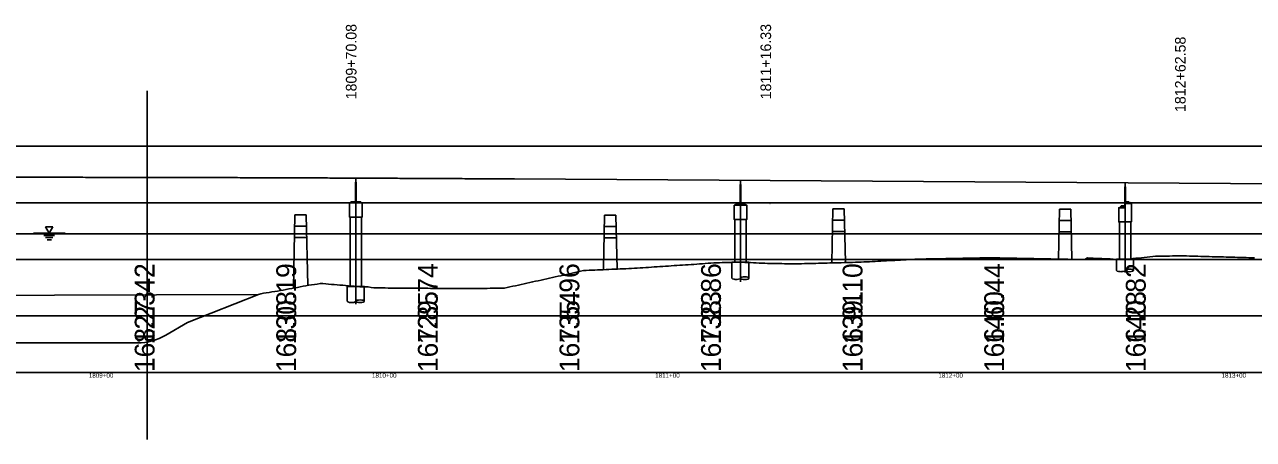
# Model space of a CAD drawing. Extents: x 2126510 to 2136144, y 865066 to 868066.
# Drawn here: x 2129321.8 to 2129755.8, y 866590.3 to 866736.8 of the extents above; entities that cross this region are included whole.
import ezdxf

# ---------------------------------------------------------------- set-up
doc = ezdxf.new("R2010")
doc.units = 0
for name, color, linetype in [('RD_DTM_BkLn1', 7, 'Continuous'), ('RD_EX_Bldg', 7, 'Continuous'), ('RD_EX_BldgApp', 7, 'Continuous'), ('RD_EX_Bridge', 7, 'Continuous'), ('RD_EX_GuardRail', 7, 'Continuous'), ('RD_EX_H2O', 7, 'Continuous'), ('RD_EX_Misc', 7, 'Continuous'), ('RD_EX_Misc_Golf_Fairway', 7, 'Continuous'), ('RD_HC_Data', 7, 'Continuous'), ('RD_HC_txCode', 7, 'Continuous')]:
    doc.layers.add(name, color=color, linetype=linetype)

msp = doc.modelspace()

# ---------------------------------------------------------------- linework, layer by layer
at = {"layer": 'RD_DTM_BkLn1'}
for p, q in [((2129440.54, 866674.17), (2129437.04, 866674.17)), ((2129437.04, 866674.17), (2129437.04, 866673.84)), ((2129437.46, 866674.17), (2129440.13, 866674.17)), ((2129440.54, 866673.84), (2129440.54, 866674.17)), ((2129576.38, 866673.37), (2129572.88, 866673.37)), ((2129572.88, 866673.37), (2129572.88, 866673.03)), ((2129573.29, 866673.37), (2129575.96, 866673.37)), ((2129576.38, 866673.03), (2129576.38, 866673.37)), ((2129710.46, 866673.97), (2129712.21, 866673.97)), ((2129710.46, 866673.97), (2129710.46, 866673.6)), ((2129710.46, 866672.14), (2129710.46, 866673.6)), ((2129712.71, 866673.6), (2129710.46, 866673.6)), ((2129712.21, 866673.97), (2129712.21, 866673.6)), ((2129436.79, 866668.84), (2129436.79, 866644.34)), ((2129440.79, 866668.84), (2129440.79, 866644.34)), ((2129710.46, 866672.51), (2129708.71, 866672.51)), ((2129708.71, 866672.51), (2129708.71, 866672.14)), ((2129572.63, 866668.03), (2129572.63, 866652.88)), ((2129576.63, 866668.03), (2129576.63, 866652.88)), ((2129708.46, 866667.14), (2129708.46, 866653.94)), ((2129712.46, 866667.14), (2129712.46, 866653.94))]:
    msp.add_line(p, q, dxfattribs=at)
for points in [[(2129436.54, 866673.84), (2129441.04, 866673.84), (2129441.04, 866668.84), (2129436.54, 866668.84)], [(2129572.38, 866673.03), (2129576.88, 866673.03), (2129576.88, 866668.03), (2129572.38, 866668.03)]]:
    msp.add_lwpolyline(points, close=True, dxfattribs=at)
for points in [[(2129712.71, 866673.6), (2129712.71, 866667.14), (2129708.21, 866667.14), (2129708.21, 866672.14), (2129710.46, 866672.14)], [(2129571.63, 866647.25), (2129571.63, 866652.88), (2129577.63, 866652.88), (2129577.63, 866647.25)], [(2129707.46, 866650), (2129707.46, 866653.94), (2129713.46, 866653.94), (2129713.46, 866650)], [(2129435.79, 866639.1), (2129435.79, 866644.34), (2129441.79, 866644.34), (2129441.79, 866639.1)]]:
    msp.add_lwpolyline(points, dxfattribs=at)
for centre in [(2129573.13, 866647.25), (2129708.96, 866650), (2129437.29, 866639.1)]:
    msp.add_ellipse(centre, major_axis=(-1.5, 0), ratio=0.310397, start_param=0, end_param=3.141593, dxfattribs=at)
for centre in [(2129576.13, 866647.25), (2129711.96, 866650), (2129440.29, 866639.1)]:
    msp.add_ellipse(centre, major_axis=(-1.5, 0), ratio=0.310397, dxfattribs=at)
at = {"layer": 'RD_EX_Bldg'}
for p, q in [((2129711.79, 866673.97), (2129710.46, 866673.97)), ((2129709.12, 866672.51), (2129710.46, 866672.51))]:
    msp.add_line(p, q, dxfattribs=at)
at = {"layer": 'RD_EX_BldgApp'}
for p, q in [((2129329.23, 866665.37), (2129331.85, 866665.37)), ((2129330.54, 866663.1), (2129329.23, 866665.37)), ((2129331.85, 866665.37), (2129330.54, 866663.1)), ((2129324.92, 866663.1), (2129336.17, 866663.1)), ((2129328.67, 866662.35), (2129332.42, 866662.35)), ((2129329.23, 866661.6), (2129331.85, 866661.6)), ((2129329.79, 866660.85), (2129331.29, 866660.85))]:
    msp.add_line(p, q, dxfattribs=at)
at = {"layer": 'RD_EX_Bridge'}
for p, q in [((2129437.46, 866674.46), (2129437.46, 866674.17)), ((2129438.46, 866674.46), (2129438.46, 866674.17)), ((2129439.13, 866674.17), (2129439.13, 866674.46)), ((2129440.13, 866674.17), (2129440.13, 866674.46)), ((2129573.29, 866673.66), (2129573.29, 866673.37)), ((2129574.29, 866673.66), (2129574.29, 866673.37)), ((2129574.96, 866673.37), (2129574.96, 866673.66)), ((2129575.96, 866673.37), (2129575.96, 866673.66)), ((2129710.12, 866672.8), (2129709.12, 866672.8)), ((2129709.12, 866672.8), (2129709.12, 866672.51)), ((2129710.12, 866672.8), (2129710.12, 866672.51)), ((2129710.79, 866674.26), (2129711.79, 866674.26)), ((2129710.79, 866673.97), (2129710.79, 866674.26)), ((2129711.79, 866674.26), (2129711.79, 866673.97))]:
    msp.add_line(p, q, dxfattribs=at)
at = {"layer": 'RD_EX_GuardRail'}
for p, q in [((2131097.7, 866693.9), (2126517.45, 866693.9)), ((2131097.7, 866673.9), (2129000.13, 866673.9)), ((2131097.7, 866653.9), (2126517.45, 866653.9)), ((2131097.7, 866633.9), (2126517.45, 866633.9)), ((2131097.7, 866613.9), (2126517.45, 866613.9))]:
    msp.add_line(p, q, dxfattribs=at)
at = {"layer": 'RD_EX_H2O'}
msp.add_line((2129043.31, 866624.4), (2129361.63, 866624.4), dxfattribs=at)
for points in [[(2129532.19, 866650.52), (2129533.19, 866650.56), (2129534.19, 866650.6), (2129535.19, 866650.65), (2129536.19, 866650.69), (2129537.19, 866650.74), (2129538.19, 866650.8), (2129539.19, 866650.86), (2129540.19, 866650.93), (2129541.19, 866651), (2129542.19, 866651.06), (2129543.19, 866651.13), (2129544.19, 866651.2), (2129545.19, 866651.27), (2129546.19, 866651.33), (2129547.19, 866651.4), (2129548.19, 866651.47), (2129549.19, 866651.53), (2129550.19, 866651.6), (2129551.19, 866651.67), (2129552.19, 866651.73), (2129553.19, 866651.8), (2129554.19, 866651.87), (2129555.19, 866651.93), (2129556.19, 866652), (2129557.19, 866652.07), (2129558.19, 866652.14), (2129559.19, 866652.2), (2129560.19, 866652.27), (2129561.19, 866652.37), (2129562.19, 866652.46), (2129563.19, 866652.56), (2129564.19, 866652.61), (2129565.19, 866652.64), (2129566.19, 866652.68), (2129567.19, 866652.71), (2129568.19, 866652.75), (2129569.19, 866652.78), (2129570.19, 866652.81), (2129571.19, 866652.83), (2129572.19, 866652.85), (2129573.19, 866652.87), (2129574.19, 866652.9), (2129575.19, 866652.87), (2129576.19, 866652.82), (2129577.19, 866652.78), (2129578.19, 866652.73), (2129579.19, 866652.69), (2129580.19, 866652.64), (2129581.19, 866652.6), (2129582.19, 866652.56), (2129583.19, 866652.51), (2129584.19, 866652.47), (2129585.19, 866652.42), (2129586.19, 866652.38), (2129587.19, 866652.38), (2129588.19, 866652.38), (2129589.19, 866652.38), (2129590.19, 866652.36), (2129591.19, 866652.34), (2129592.19, 866652.36), (2129593.19, 866652.36), (2129594.19, 866652.37), (2129595.19, 866652.37), (2129596.19, 866652.37), (2129597.19, 866652.39), (2129598.19, 866652.41), (2129599.19, 866652.44), (2129600.19, 866652.46), (2129601.19, 866652.49), (2129602.19, 866652.52), (2129603.19, 866652.54), (2129604.19, 866652.57), (2129605.19, 866652.59), (2129606.19, 866652.62), (2129607.19, 866652.65), (2129608.19, 866652.67), (2129609.19, 866652.7), (2129610.19, 866652.72), (2129611.19, 866652.75), (2129612.19, 866652.78), (2129613.19, 866652.8), (2129614.19, 866652.83), (2129615.19, 866652.85), (2129616.19, 866652.89), (2129617.19, 866652.92), (2129618.19, 866652.97), (2129619.19, 866653.02), (2129620.19, 866653.08), (2129621.19, 866653.13), (2129622.19, 866653.18), (2129623.19, 866653.23), (2129624.19, 866653.28), (2129625.19, 866653.34), (2129626.19, 866653.39), (2129627.19, 866653.44), (2129628.19, 866653.49), (2129629.19, 866653.55), (2129630.19, 866653.6), (2129631.19, 866653.65), (2129632.19, 866653.7)], [(2129632.19, 866653.7), (2129633.19, 866653.76), (2129634.19, 866653.81), (2129635.19, 866653.86), (2129636.19, 866653.91), (2129637.19, 866653.96), (2129638.19, 866653.99), (2129639.19, 866654.01), (2129640.19, 866654.03), (2129641.19, 866654.05), (2129642.19, 866654.07), (2129643.19, 866654.08), (2129644.19, 866654.1), (2129645.19, 866654.12), (2129646.19, 866654.14), (2129647.19, 866654.16), (2129648.19, 866654.18), (2129649.19, 866654.2), (2129650.19, 866654.21), (2129651.19, 866654.23), (2129652.19, 866654.25), (2129653.19, 866654.27), (2129654.19, 866654.29), (2129655.19, 866654.31), (2129656.19, 866654.32), (2129657.19, 866654.34), (2129658.19, 866654.36), (2129659.19, 866654.38), (2129660.19, 866654.4), (2129661.19, 866654.42), (2129662.19, 866654.45), (2129663.19, 866654.47), (2129664.19, 866654.45), (2129665.19, 866654.41), (2129666.19, 866654.39), (2129667.19, 866654.37), (2129668.19, 866654.35), (2129669.19, 866654.33), (2129670.19, 866654.31), (2129671.19, 866654.29), (2129672.19, 866654.27), (2129673.19, 866654.25), (2129674.19, 866654.23), (2129675.19, 866654.21), (2129676.19, 866654.19), (2129677.19, 866654.17), (2129678.19, 866654.15), (2129679.19, 866654.13), (2129680.19, 866654.12), (2129681.19, 866654.1), (2129682.19, 866654.08), (2129683.19, 866654.06), (2129684.19, 866654.04), (2129685.19, 866654.02), (2129686.19, 866654), (2129687.19, 866653.98), (2129688.19, 866653.96), (2129689.19, 866653.94), (2129690.19, 866653.92), (2129691.19, 866653.9), (2129692.19, 866653.88), (2129693.19, 866653.86), (2129694.19, 866653.84), (2129695.19, 866653.82), (2129696.19, 866653.85), (2129697.19, 866654.4), (2129698.19, 866654.35), (2129699.19, 866654.31), (2129700.19, 866654.26), (2129701.19, 866654.21), (2129702.19, 866654.17), (2129703.19, 866654.12), (2129704.19, 866654.07), (2129705.19, 866654.03), (2129706.19, 866653.97), (2129707.19, 866653.89), (2129708.19, 866653.81), (2129709.19, 866653.86), (2129710.19, 866653.92), (2129711.19, 866653.98), (2129712.19, 866654.08), (2129713.19, 866654.18), (2129714.19, 866654.28), (2129715.19, 866654.37), (2129716.19, 866654.47), (2129717.19, 866654.57), (2129718.19, 866654.67), (2129719.19, 866654.77), (2129720.19, 866654.87), (2129721.19, 866654.97), (2129722.19, 866655), (2129723.19, 866654.97), (2129724.19, 866655.01), (2129725.19, 866655.02), (2129726.19, 866655.05), (2129727.19, 866655.09), (2129728.19, 866655.13), (2129729.19, 866655.17), (2129730.19, 866655.14), (2129731.19, 866655.11), (2129732.19, 866655.09)], [(2129732.19, 866655.09), (2129733.19, 866655.06), (2129734.19, 866655.03), (2129735.19, 866655.01), (2129736.19, 866654.98), (2129737.19, 866654.95), (2129738.19, 866654.93), (2129739.19, 866654.9), (2129740.19, 866654.87), (2129741.19, 866654.84), (2129742.19, 866654.82), (2129743.19, 866654.79), (2129744.19, 866654.76), (2129745.19, 866654.74), (2129746.19, 866654.71), (2129747.19, 866654.68), (2129748.19, 866654.66), (2129749.19, 866654.63), (2129750.19, 866654.6), (2129751.19, 866654.57), (2129752.19, 866654.55), (2129753.19, 866654.52), (2129754.19, 866654.49), (2129755.19, 866654.47), (2129756.19, 866654.45)], [(2129432.19, 866644.9), (2129433.19, 866644.82), (2129434.19, 866644.73), (2129435.19, 866644.65), (2129436.19, 866644.56), (2129437.19, 866644.48), (2129438.19, 866644.39), (2129439.19, 866644.31), (2129440.19, 866644.22), (2129441.19, 866644.17), (2129442.19, 866644.17), (2129443.19, 866644.18), (2129444.19, 866643.98), (2129445.19, 866643.85), (2129446.19, 866643.83), (2129447.19, 866643.81), (2129448.19, 866643.79), (2129449.19, 866643.78), (2129450.19, 866643.77), (2129451.19, 866643.76), (2129452.19, 866643.76), (2129453.19, 866643.75), (2129454.19, 866643.74), (2129455.19, 866643.73), (2129456.19, 866643.73), (2129457.19, 866643.72), (2129458.19, 866643.71), (2129459.19, 866643.71), (2129460.19, 866643.7), (2129461.19, 866643.69), (2129462.19, 866643.69), (2129463.19, 866643.68), (2129464.19, 866643.67), (2129465.19, 866643.66), (2129466.19, 866643.66), (2129467.19, 866643.65), (2129468.19, 866643.64), (2129469.19, 866643.64), (2129470.19, 866643.63), (2129471.19, 866643.62), (2129472.19, 866643.62), (2129473.19, 866643.61), (2129474.19, 866643.6), (2129475.19, 866643.6), (2129476.19, 866643.59), (2129477.19, 866643.58), (2129478.19, 866643.57), (2129479.19, 866643.57), (2129480.19, 866643.56), (2129481.19, 866643.55), (2129482.19, 866643.55), (2129483.19, 866643.55), (2129484.19, 866643.59), (2129485.19, 866643.63), (2129486.19, 866643.67), (2129487.19, 866643.71), (2129488.19, 866643.73), (2129489.19, 866643.72), (2129490.19, 866643.71), (2129491.19, 866643.72), (2129492.19, 866643.94), (2129493.19, 866644.16), (2129494.19, 866644.38), (2129495.19, 866644.6), (2129496.19, 866644.82), (2129497.19, 866645.04), (2129498.19, 866645.26), (2129499.19, 866645.48), (2129500.19, 866645.7), (2129501.19, 866645.92), (2129502.19, 866646.15), (2129503.19, 866646.37), (2129504.19, 866646.59), (2129505.19, 866646.81), (2129506.19, 866647.03), (2129507.19, 866647.25), (2129508.19, 866647.47), (2129509.19, 866647.69), (2129510.19, 866647.91), (2129511.19, 866648.13), (2129512.19, 866648.35), (2129513.19, 866648.57), (2129514.19, 866648.79), (2129515.19, 866649.01), (2129516.19, 866649.26), (2129517.19, 866649.52), (2129518.19, 866649.78), (2129519.19, 866649.94), (2129520.19, 866649.99), (2129521.19, 866650.03), (2129522.19, 866650.08), (2129523.19, 866650.12), (2129524.19, 866650.16), (2129525.19, 866650.21), (2129526.19, 866650.25), (2129527.19, 866650.3), (2129528.19, 866650.34), (2129529.19, 866650.38), (2129530.19, 866650.43), (2129531.19, 866650.47), (2129532.19, 866650.52)], [(2129404.47, 866641.43), (2129405.19, 866641.67), (2129406.19, 866641.95), (2129407.19, 866642.09), (2129408.19, 866642.23), (2129409.19, 866642.37), (2129410.19, 866642.51), (2129411.19, 866642.68), (2129412.19, 866642.87), (2129413.19, 866643.06), (2129414.19, 866643.25), (2129415.19, 866643.43), (2129416.19, 866643.62), (2129417.19, 866643.81), (2129418.19, 866643.99), (2129419.19, 866644.18), (2129420.19, 866644.37), (2129421.19, 866644.56), (2129422.19, 866644.74), (2129423.19, 866644.9), (2129424.19, 866645.04), (2129425.19, 866645.19), (2129426.19, 866645.34), (2129427.19, 866645.32), (2129428.19, 866645.24), (2129429.19, 866645.15), (2129430.19, 866645.07), (2129431.19, 866644.99), (2129432.19, 866644.9)], [(2129404.47, 866641.43), (2129379.32, 866631.56), (2129371.69, 866627.12)]]:
    msp.add_lwpolyline(points, dxfattribs=at)
msp.add_arc((2129361.63, 866644.4), 20, 270, 300.189, dxfattribs=at)
at = {"layer": 'RD_EX_Misc'}
for p, q in [((2129365.16, 866713.42), (2129365.16, 866590.28)), ((2129494.88, 866682.29), (2130513.48, 866675.88)), ((2127368.72, 866613.9), (2131522.97, 866613.9))]:
    msp.add_line(p, q, dxfattribs=at)
for points in [[(2127275.85, 866613.9), (2127275.85, 866662.9), (2131989.68, 866662.9)], [(2129008.05, 866640.24), (2129404.47, 866641.43)]]:
    msp.add_lwpolyline(points, dxfattribs=at)
msp.add_spline([(2129142.37, 866682.52), (2129149.42, 866682.56), (2129156.47, 866682.59), (2129163.52, 866682.62), (2129170.57, 866682.65), (2129177.62, 866682.68), (2129184.67, 866682.7), (2129191.72, 866682.73), (2129198.77, 866682.75), (2129205.82, 866682.77), (2129212.87, 866682.79), (2129219.92, 866682.81), (2129226.97, 866682.83), (2129234.02, 866682.85), (2129241.07, 866682.86), (2129248.12, 866682.87), (2129255.17, 866682.88), (2129262.23, 866682.89), (2129269.28, 866682.9), (2129276.33, 866682.9), (2129283.38, 866682.91), (2129290.43, 866682.91), (2129297.48, 866682.91), (2129304.53, 866682.91), (2129311.58, 866682.91), (2129318.63, 866682.9), (2129325.68, 866682.9), (2129332.73, 866682.89), (2129339.78, 866682.88), (2129346.83, 866682.87), (2129353.88, 866682.86), (2129360.93, 866682.85), (2129367.98, 866682.83), (2129375.03, 866682.82), (2129382.08, 866682.8), (2129389.13, 866682.78), (2129396.18, 866682.76), (2129403.23, 866682.74), (2129410.28, 866682.71), (2129417.33, 866682.68), (2129424.38, 866682.66), (2129431.43, 866682.63), (2129438.48, 866682.6), (2129445.53, 866682.56), (2129452.58, 866682.53), (2129459.63, 866682.49), (2129466.68, 866682.46), (2129473.73, 866682.42), (2129480.78, 866682.38), (2129487.83, 866682.34), (2129494.88, 866682.29)], degree=3, dxfattribs=at)
at = {"layer": 'RD_EX_Misc_Golf_Fairway'}
for p, q in [((2129417.28, 866669.65), (2129416.74, 866643.72)), ((2129421.28, 866669.65), (2129417.28, 866669.65)), ((2129421.28, 866669.65), (2129421.8, 866644.67)), ((2129526.66, 866669.47), (2129526.26, 866650.26)), ((2129530.66, 866669.47), (2129526.66, 866669.47)), ((2129530.66, 866669.47), (2129531.05, 866650.47)), ((2129607.28, 866671.79), (2129606.88, 866652.64)), ((2129611.28, 866671.79), (2129607.28, 866671.79)), ((2129611.28, 866671.79), (2129611.68, 866652.76)), ((2129687.28, 866671.63), (2129686.92, 866653.98)), ((2129691.28, 866671.63), (2129687.28, 866671.63)), ((2129691.28, 866671.63), (2129691.65, 866653.89)), ((2129421.37, 866665.65), (2129417.21, 866665.65)), ((2129530.74, 866665.47), (2129526.59, 866665.47)), ((2129611.37, 866667.79), (2129607.21, 866667.79)), ((2129691.37, 866667.63), (2129687.21, 866667.63)), ((2129421.45, 866661.65), (2129417.12, 866661.65)), ((2129530.82, 866661.47), (2129526.49, 866661.47)), ((2129611.45, 866663.79), (2129607.12, 866663.79)), ((2129691.45, 866663.63), (2129687.12, 866663.63))]:
    msp.add_line(p, q, dxfattribs=at)
at = {"layer": 'RD_HC_Data'}
for p, q in [((2129438.79, 866682.65), (2129438.79, 866638.06)), ((2129574.63, 866681.79), (2129574.63, 866646.01)), ((2129710.46, 866680.93), (2129710.46, 866649.24)), ((2129584.96, 866673.59), (2129585.13, 866673.59))]:
    msp.add_line(p, q, dxfattribs=at)
at = {"layer": 'RD_HC_txCode'}
for p, q in [((2129438.71, 866681.17), (2129438.71, 866674.46)), ((2129438.88, 866681.17), (2129438.88, 866674.46)), ((2129574.54, 866680.37), (2129574.54, 866673.66)), ((2129574.71, 866680.37), (2129574.71, 866673.66)), ((2129710.37, 866679.51), (2129710.37, 866672.8)), ((2129710.54, 866679.51), (2129710.54, 866674.26))]:
    msp.add_line(p, q, dxfattribs=at)

# ---------------------------------------------------------------- texts
at = {"layer": 'RD_EX_Misc'}
for s, height, p in [('1809+70.08', 3.75, (2129439.03, 866710.43)), ('1811+16.33', 3.75, (2129585.45, 866710.43)), ('1812+62.58', 3.75, (2129731.83, 866705.94)), ('127.42', 7, (2129367.72, 866623.9)), ('130.19', 7, (2129417.72, 866623.9)), ('129.74', 7, (2129467.72, 866623.9)), ('135.96', 7, (2129517.72, 866623.9)), ('138.86', 7, (2129567.72, 866623.9)), ('139.10', 7, (2129617.72, 866623.9)), ('140.44', 7, (2129667.72, 866623.9)), ('140.82', 7, (2129717.72, 866623.9)), ('167.54', 7, (2129517.72, 866614.05)), ('166.60', 7, (2129667.72, 866614.05)), ('168.23', 7, (2129367.72, 866614.05)), ('168.08', 7, (2129417.72, 866614.05)), ('167.85', 7, (2129467.72, 866614.05)), ('167.23', 7, (2129567.72, 866614.05)), ('166.91', 7, (2129617.72, 866614.05)), ('166.28', 7, (2129717.72, 866614.05))]:
    msp.add_text(s, height=height, rotation=90, dxfattribs=at).set_placement(p)
for s, p in [('1809+00', (2129344.51, 866612.1)), ('1810+00', (2129444.51, 866612.1)), ('1811+00', (2129544.51, 866612.1)), ('1812+00', (2129644.51, 866612.1)), ('1813+00', (2129744.51, 866612.1))]:
    msp.add_text(s, height=1.6, dxfattribs=at).set_placement(p)

doc.saveas('drawing.dxf')
